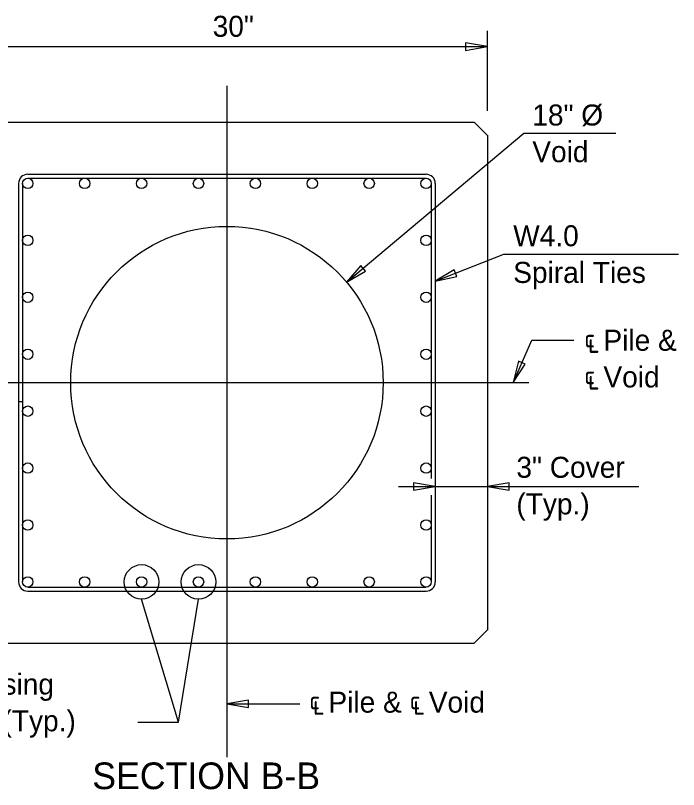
# Model space of a CAD drawing. Extents: x 112310.1 to 112345.4, y 111943.5 to 111959.3.
# Drawn here: x 112315.17 to 112318.353, y 111948.504 to 111952.219 of the extents above; entities that cross this region are included whole.
import ezdxf

# ---------------------------------------------------------------- set-up
doc = ezdxf.new("R2010")
doc.units = 0
for name, color, linetype in [('CL_Major', 7, 'Continuous'), ('Dimension', 7, 'Continuous'), ('PileConc', 7, 'Continuous'), ('Rebar', 7, 'Continuous'), ('TextStructures', 7, 'Continuous')]:
    doc.layers.add(name, color=color, linetype=linetype)

msp = doc.modelspace()

# ---------------------------------------------------------------- linework, layer by layer
at = {"layer": 'CL_Major'}
for p, q in [((112316.1851, 111951.8819), (112316.1851, 111950.4568)), ((112316.1851, 111950.4568), (112314.6326, 111950.4568)), ((112316.1851, 111950.4568), (112316.1851, 111948.6593)), ((112317.635, 111950.4568), (112316.1851, 111950.4568))]:
    msp.add_line(p, q, dxfattribs=at)
at = {"layer": 'Dimension'}
for p, q in [((112317.4353, 111951.7606), (112317.4353, 111952.1445)), ((112314.9353, 111952.0693), (112317.4353, 111952.0693)), ((112316.7596, 111950.9391), (112317.6111, 111951.654)), ((112317.6111, 111951.654), (112318.0519, 111951.654)), ((112317.1853, 111950.9447), (112317.5149, 111951.0735)), ((112317.5149, 111951.0735), (112318.3531, 111951.0735)), ((112317.0095, 111949.9593), (112317.1853, 111949.9593)), ((112317.1853, 111949.9593), (112317.4353, 111949.9593)), ((112317.4353, 111949.9593), (112318.163, 111949.9593)), ((112315.9527, 111948.8274), (112315.7753, 111949.4177)), ((112315.9527, 111948.8274), (112316.0485, 111949.4177)), ((112316.1853, 111948.9155), (112316.5349, 111948.9155)), ((112315.7575, 111948.8274), (112315.9526, 111948.8274))]:
    msp.add_line(p, q, dxfattribs=at)
for points in [[(112317.4353, 111952.0693), (112317.3311, 111952.0869), (112317.3311, 111952.0516)], [(112316.7596, 111950.9391), (112316.8507, 111950.9926), (112316.828, 111951.0196)], [(112317.1853, 111950.9447), (112317.2887, 111950.9662), (112317.2758, 111950.999)], [(112317.5594, 111950.457), (112317.6175, 111950.5452), (112317.5852, 111950.5594)], [(112317.1853, 111949.9593), (112317.0811, 111949.9769), (112317.0811, 111949.9416)], [(112317.4353, 111949.9593), (112317.5394, 111949.9416), (112317.5394, 111949.9769)], [(112316.1853, 111948.9155), (112316.2894, 111948.8978), (112316.2894, 111948.9331)]]:
    msp.add_lwpolyline(points, close=True, dxfattribs=at)
msp.add_lwpolyline([(112317.5592, 111950.4568), (112317.6489, 111950.6606), (112317.8504, 111950.6606)], dxfattribs=at)
for centre in [(112315.7753, 111949.5006), (112316.0485, 111949.5006)]:
    msp.add_circle(centre, 0.083, dxfattribs=at)
at = {"layer": 'PileConc'}
for p, q in [((112314.9978, 111951.7069), (112317.3728, 111951.7069)), ((112317.3726, 111951.7068), (112317.4351, 111951.6443)), ((112317.4353, 111951.6444), (112317.4353, 111949.2694)), ((112317.3726, 111949.2068), (112317.4351, 111949.2693)), ((112314.9978, 111949.2069), (112317.3728, 111949.2069))]:
    msp.add_line(p, q, dxfattribs=at)
msp.add_circle((112316.1851, 111950.4568), 0.75, dxfattribs=at)
at = {"layer": 'Rebar'}
for p, q in [((112315.2291, 111951.4569), (112317.1415, 111951.4569)), ((112315.1853, 111951.4131), (112315.1853, 111949.5007)), ((112315.2041, 111951.4131), (112315.2041, 111949.5007)), ((112315.2291, 111951.4381), (112317.1415, 111951.4381)), ((112317.1663, 111951.413), (112317.1663, 111949.9976)), ((112317.1853, 111951.4131), (112317.1853, 111949.5007)), ((112315.2039, 111950.3642), (112315.1851, 111950.3642)), ((112317.1663, 111949.9172), (112317.1663, 111949.5006)), ((112315.2291, 111949.4757), (112317.1415, 111949.4757)), ((112315.2291, 111949.4569), (112317.1415, 111949.4569))]:
    msp.add_line(p, q, dxfattribs=at)
for centre in [(112315.2289, 111951.413), (112315.5021, 111951.413), (112315.7753, 111951.413), (112316.0485, 111951.413), (112316.3217, 111951.413), (112316.5949, 111951.413), (112316.8681, 111951.413), (112317.1413, 111951.413), (112315.2289, 111951.1398), (112317.1413, 111951.1398), (112315.2289, 111950.8666), (112317.1413, 111950.8666), (112315.2289, 111950.5934), (112317.1413, 111950.5934), (112315.2289, 111950.3202), (112317.1413, 111950.3202), (112315.2289, 111950.047), (112317.1413, 111950.047), (112315.2289, 111949.7738), (112317.1413, 111949.7738), (112315.2289, 111949.5006), (112315.5021, 111949.5006), (112315.7753, 111949.5006), (112316.0485, 111949.5006), (112316.3217, 111949.5006), (112316.5949, 111949.5006), (112316.8681, 111949.5006), (112317.1413, 111949.5006)]:
    msp.add_circle(centre, 0.025, dxfattribs=at)
for centre, start, end in [((112315.2289, 111951.413), 90, 180), ((112317.1413, 111951.413), 0, 90), ((112315.2289, 111949.5006), 180, 270), ((112317.1413, 111949.5006), 270, 0)]:
    msp.add_arc(centre, 0.0438, start, end, dxfattribs=at)

# ---------------------------------------------------------------- texts
at = {"layer": 'Dimension'}
for s, p in [('18" Ø', (112317.6511, 111951.6908)), ('Void', (112317.6511, 111951.5148)), ('W4.0 ', (112317.5595, 111951.1114)), ('Spiral Ties', (112317.5595, 111950.9354)), ('℄ Pile &', (112317.9005, 111950.61)), ('℄ Void', (112317.9005, 111950.434)), ('3" Cover', (112317.5747, 111950.0004)), ('(Typ.)', (112317.5747, 111949.8244)), ('Prestressing', (112314.6057, 111948.9598)), ('Strands (Typ.)', (112314.6057, 111948.7838))]:
    msp.add_text(s, height=0.1008, dxfattribs=at).set_placement(p)
at = {"layer": 'TextStructures'}
for s, height, p in [('30"', 0.1008, (112316.1167, 111952.1166)), ('℄ Pile & ℄ Void', 0.1008, (112316.5803, 111948.8734)), ('SECTION B-B', 0.128, (112315.5385, 111948.5063))]:
    msp.add_text(s, height=height, dxfattribs=at).set_placement(p)

doc.saveas('drawing.dxf')
